(* Logix 5000 project; controller AMCI_3202_AOP_AOI_sample_RSLogix_V28 vendor 1 type 14 code 92 rev 28.11; software revision 28.00; part 3 of 3 *)
(* tags used below, declared in another part *)
   AMCI_3202_ch2_config_AOI : AMCI_3202_AOP_Configure;
   AMCI_3202_ch2_Home_CW_AOI : AMCI_3202_AOP_Home_CW;
   AMCI_3202_ch2_Manual_Move_CCW_AOI : AMCI_3202_AOP_Manual_Move_CCW;
   AMCI_3202_ch2_Manual_Move_CW_AOI : AMCI_3202_AOP_Manual_Move_CW;
   AMCI_3202_ch2_Preset_AOI : AMCI_3202_AOP_Preset;
   AMCI_3202_ch2_relative_move_AOI : AMCI_3202_AOP_Relative_Move;
   AMCI_3202_ch2_reset_errors_AOI : AMCI_3202_AOP_Reset_Errors;
   AMCI_3202_ch2_run_blend_AOI : AMCI_3202_AOP_Run_Blend;
   blend_message_3202_ch2 : MESSAGE;
   buffered_3202_data : DINT[16];
   comment : INT;
   run_3202_ch2 : INT;   // 1=Relative move 2=CW Manual Move 3=CCW Manual Move 4=Reset Errors 5=Home CW 6=Preset 7=Program Blend 8=Run Blend CW
(* MainProgram, continued *)

ROUTINE channel_2_3202   (* ladder *)
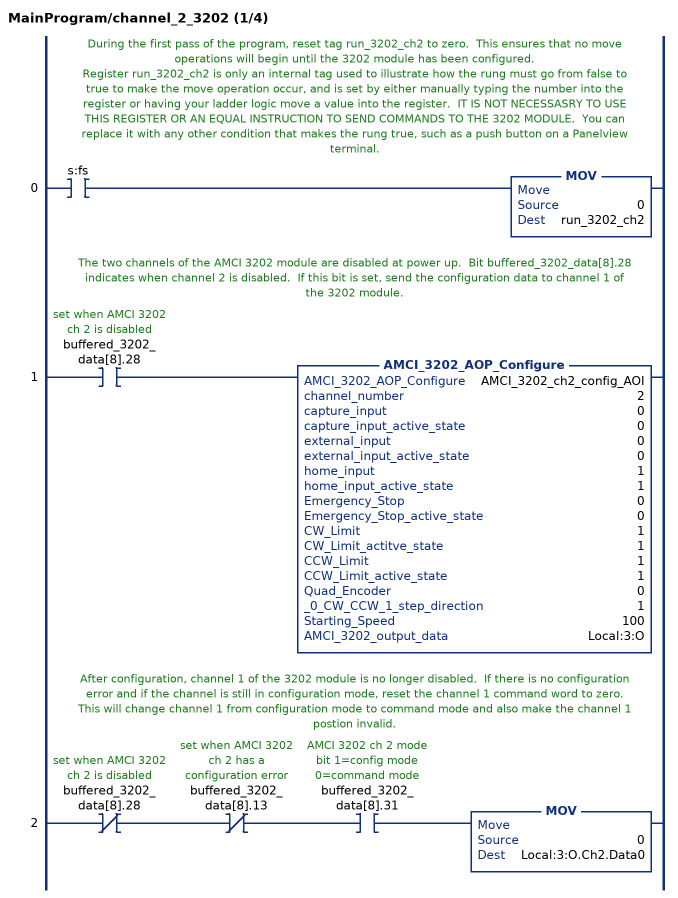
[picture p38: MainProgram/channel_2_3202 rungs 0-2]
   // During the first pass of the program, reset tag run_3202_ch2 to zero.  This ensures that no move operations will begin until the 3202 module has been configured.
   // Register run_3202_ch2 is only an internal tag used to illustrate how the rung must go from false to true to make the move operation occur, and is set by either manually typing the number into the register or having your ladder logic move a value into the register.  IT IS NOT NECESSASRY TO USE THIS REGISTER OR AN EQUAL INSTRUCTION TO SEND COMMANDS TO THE 3202 MODULE.  You can replace it with any other condition that makes the rung true, such as a push button on a Panelview terminal.
   0: XIC(s:fs)MOV(0,run_3202_ch2);
   // The two channels of the AMCI 3202 module are disabled at power up.  Bit buffered_3202_data[8].28 indicates when channel 2 is disabled.  If this bit is set, send the configuration data to channel 1 of the 3202 module.
   1: XIC(buffered_3202_data[8].28)AMCI_3202_AOP_Configure(AMCI_3202_ch2_config_AOI,2,0,0,0,0,1,1,0,0,1,1,1,1,0,1,100,Local:3:O);
   // After configuration, channel 1 of the 3202 module is no longer disabled.  If there is no configuration error and if the channel is still in configuration mode, reset the channel 1 command word to zero.  This will change channel 1 from configuration mode to command mode and also make the channel 1 postion invalid.
   2: XIO(buffered_3202_data[8].28)XIO(buffered_3202_data[8].13)XIC(buffered_3202_data[8].31)MOV(0,Local:3:O.Ch2.Data0);
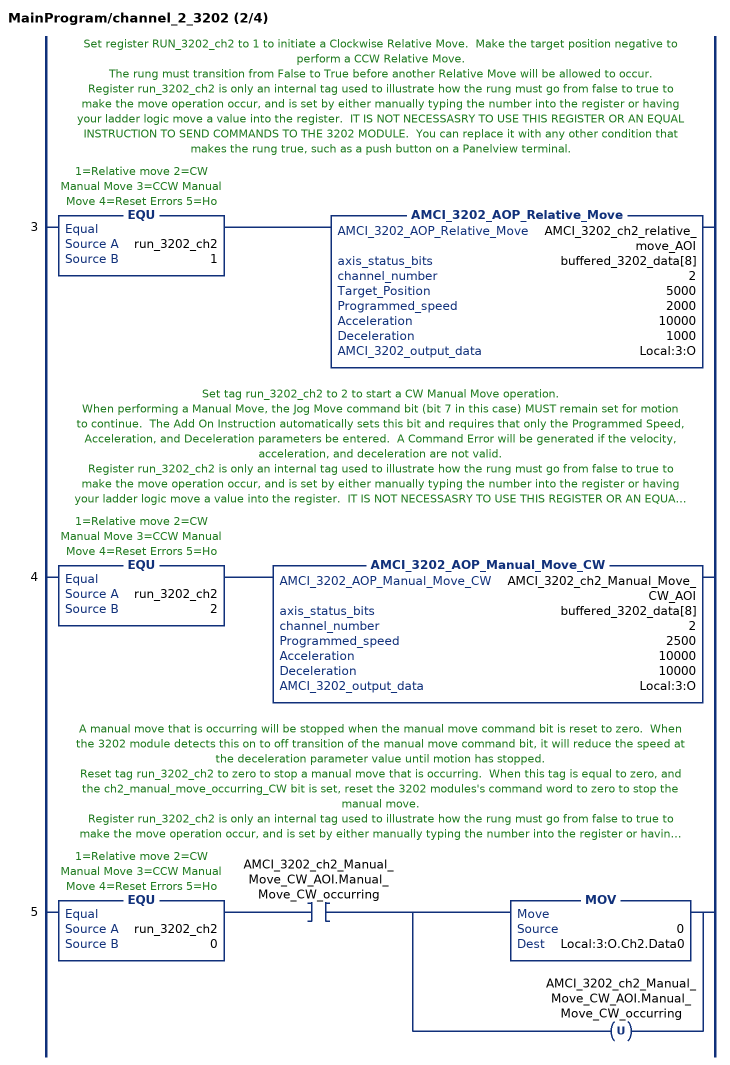
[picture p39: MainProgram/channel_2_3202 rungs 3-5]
   // Set register RUN_3202_ch2 to 1 to initiate a Clockwise Relative Move.  Make the target position negative to perform a CCW Relative Move.
   // The rung must transition from False to True before another Relative Move will be allowed to occur.
   // Register run_3202_ch2 is only an internal tag used to illustrate how the rung must go from false to true to make the move operation occur, and is set by either manually typing the number into the register or having your ladder logic move a value into the register.  IT IS NOT NECESSASRY TO USE THIS REGISTER OR AN EQUAL INSTRUCTION TO SEND COMMANDS TO THE 3202 MODULE.  You can replace it with any other condition that makes the rung true, such as a push button on a Panelview terminal.
   3: EQU(run_3202_ch2,1)AMCI_3202_AOP_Relative_Move(AMCI_3202_ch2_relative_move_AOI,buffered_3202_data[8],2,5000,2000,10000,1000,Local:3:O);
   // Set tag run_3202_ch2 to 2 to start a CW Manual Move operation.
   // When performing a Manual Move, the Jog Move command bit (bit 7 in this case) MUST remain set for motion to continue.  The Add On Instruction automatically sets this bit and requires that only the Programmed Speed, Acceleration, and Deceleration parameters be entered.  A Command Error will be generated if the velocity, acceleration, and deceleration are not valid.
   // Register run_3202_ch2 is only an internal tag used to illustrate how the rung must go from false to true to make the move operation occur, and is set by either manually typing the number into the register or having your ladder logic move a value into the register.  IT IS NOT NECESSASRY TO USE THIS REGISTER OR AN EQUAL INSTRUCTION TO SEND COMMANDS TO THE 3202 MODULE.  You can replace it with any other condition that makes the rung true, such as a push button on a Panelview terminal.
   4: EQU(run_3202_ch2,2)AMCI_3202_AOP_Manual_Move_CW(AMCI_3202_ch2_Manual_Move_CW_AOI,buffered_3202_data[8],2,2500,10000,10000,Local:3:O);
   // A manual move that is occurring will be stopped when the manual move command bit is reset to zero.  When the 3202 module detects this on to off transition of the manual move command bit, it will reduce the speed at the deceleration parameter value until motion has stopped.
   // Reset tag run_3202_ch2 to zero to stop a manual move that is occurring.  When this tag is equal to zero, and the ch2_manual_move_occurring_CW bit is set, reset the 3202 modules's command word to zero to stop the manual move.
   // Register run_3202_ch2 is only an internal tag used to illustrate how the rung must go from false to true to make the move operation occur, and is set by either manually typing the number into the register or having your ladder logic move a value into the register.  IT IS NOT NECESSASRY TO USE THIS REGISTER OR AN EQUAL INSTRUCTION TO SEND COMMANDS TO THE 3202 MODULE.  You can replace it with any other condition that makes the rung true, such as a push button on a Panelview terminal.
   5: EQU(run_3202_ch2,0)XIC(AMCI_3202_ch2_Manual_Move_CW_AOI.Manual_Move_CW_occurring)[MOV(0,Local:3:O.Ch2.Data0) ,OTU(AMCI_3202_ch2_Manual_Move_CW_AOI.Manual_Move_CW_occurring) ];
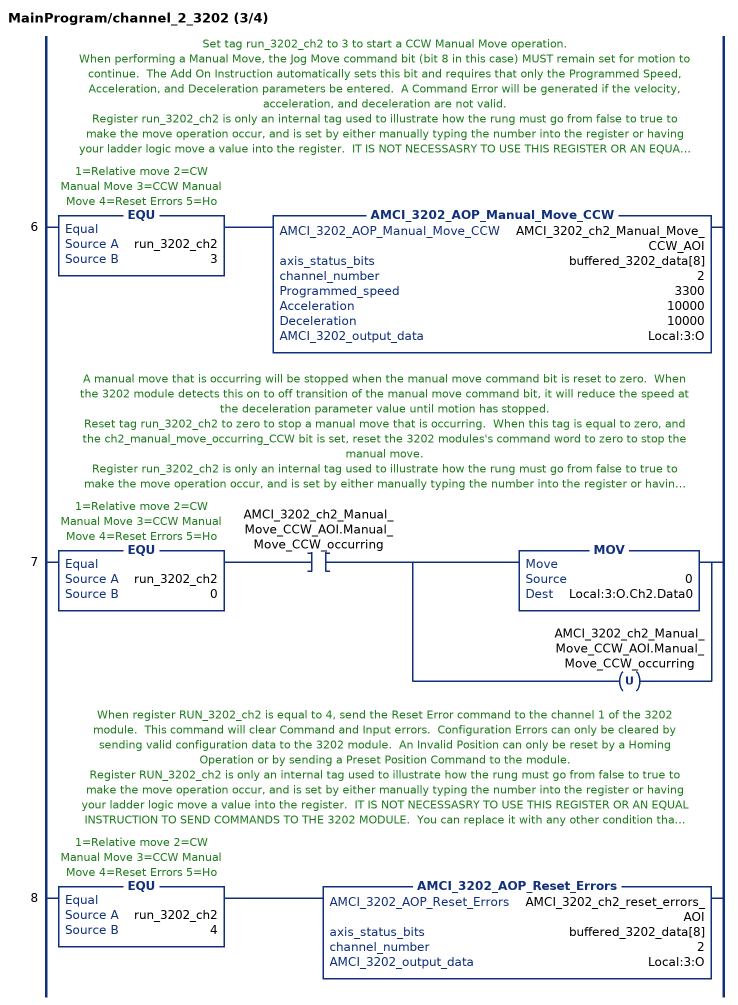
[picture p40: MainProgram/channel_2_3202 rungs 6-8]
   // Set tag run_3202_ch2 to 3 to start a CCW Manual Move operation.
   // When performing a Manual Move, the Jog Move command bit (bit 8 in this case) MUST remain set for motion to continue.  The Add On Instruction automatically sets this bit and requires that only the Programmed Speed, Acceleration, and Deceleration parameters be entered.  A Command Error will be generated if the velocity, acceleration, and deceleration are not valid.
   // Register run_3202_ch2 is only an internal tag used to illustrate how the rung must go from false to true to make the move operation occur, and is set by either manually typing the number into the register or having your ladder logic move a value into the register.  IT IS NOT NECESSASRY TO USE THIS REGISTER OR AN EQUAL INSTRUCTION TO SEND COMMANDS TO THE 3202 MODULE.  You can replace it with any other condition that makes the rung true, such as a push button on a Panelview terminal.
   6: EQU(run_3202_ch2,3)AMCI_3202_AOP_Manual_Move_CCW(AMCI_3202_ch2_Manual_Move_CCW_AOI,buffered_3202_data[8],2,3300,10000,10000,Local:3:O);
   // A manual move that is occurring will be stopped when the manual move command bit is reset to zero.  When the 3202 module detects this on to off transition of the manual move command bit, it will reduce the speed at the deceleration parameter value until motion has stopped.
   // Reset tag run_3202_ch2 to zero to stop a manual move that is occurring.  When this tag is equal to zero, and the ch2_manual_move_occurring_CCW bit is set, reset the 3202 modules's command word to zero to stop the manual move.
   // Register run_3202_ch2 is only an internal tag used to illustrate how the rung must go from false to true to make the move operation occur, and is set by either manually typing the number into the register or having your ladder logic move a value into the register.  IT IS NOT NECESSASRY TO USE THIS REGISTER OR AN EQUAL INSTRUCTION TO SEND COMMANDS TO THE 3202 MODULE.  You can replace it with any other condition that makes the rung true, such as a push button on a Panelview terminal.
   7: EQU(run_3202_ch2,0)XIC(AMCI_3202_ch2_Manual_Move_CCW_AOI.Manual_Move_CCW_occurring)[MOV(0,Local:3:O.Ch2.Data0) ,OTU(AMCI_3202_ch2_Manual_Move_CCW_AOI.Manual_Move_CCW_occurring) ];
   // When register RUN_3202_ch2 is equal to 4, send the Reset Error command to the channel 1 of the 3202 module.  This command will clear Command and Input errors.  Configuration Errors can only be cleared by sending valid configuration data to the 3202 module.  An Invalid Position can only be reset by a Homing Operation or by sending a Preset Position Command to the module.
   // Register RUN_3202_ch2 is only an internal tag used to illustrate how the rung must go from false to true to make the move operation occur, and is set by either manually typing the number into the register or having your ladder logic move a value into the register.  IT IS NOT NECESSASRY TO USE THIS REGISTER OR AN EQUAL INSTRUCTION TO SEND COMMANDS TO THE 3202 MODULE.  You can replace it with any other condition that makes the rung true, such as a push button on a Panelview terminal.
   8: EQU(run_3202_ch2,4)AMCI_3202_AOP_Reset_Errors(AMCI_3202_ch2_reset_errors_AOI,buffered_3202_data[8],2,Local:3:O);
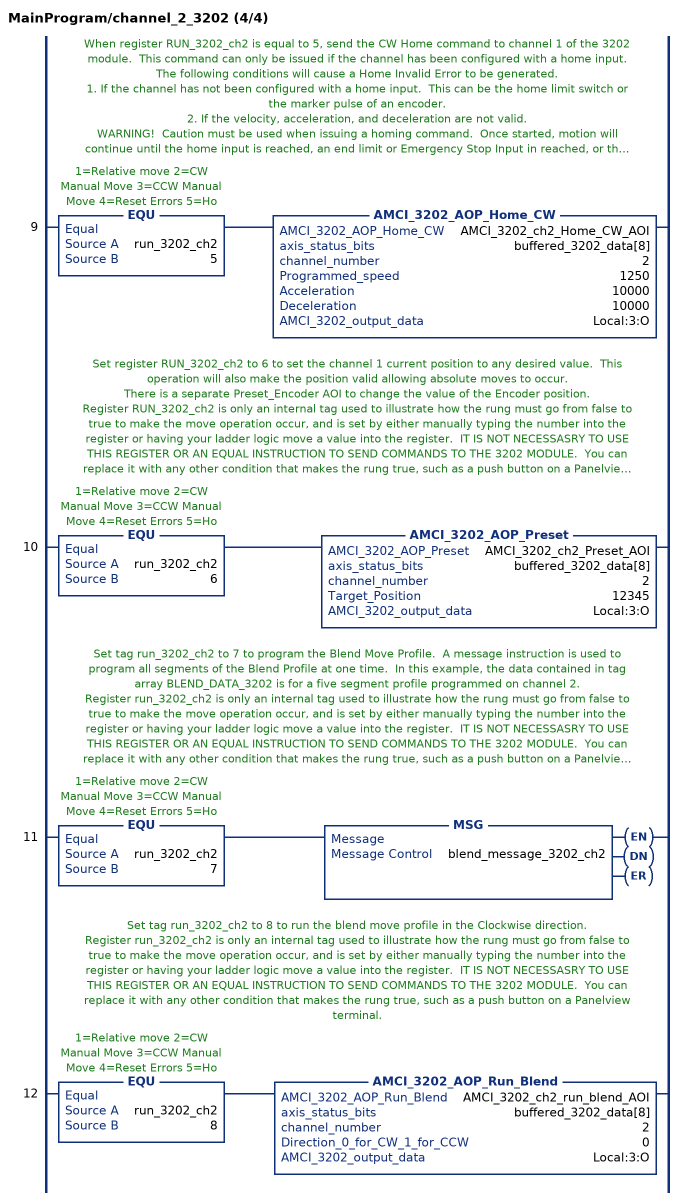
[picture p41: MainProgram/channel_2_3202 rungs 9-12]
   // When register RUN_3202_ch2 is equal to 5, send the CW Home command to channel 1 of the 3202 module.  This command can only be issued if the channel has been configured with a home input.  The following conditions will cause a Home Invalid Error to be generated.
   // 1. If the channel has not been configured with a home input.  This can be the home limit switch or the marker pulse of an encoder.
   // 2. If the velocity, acceleration, and deceleration are not valid.
   // WARNING!  Caution must be used when issuing a homing command.  Once started, motion will continue until the home input is reached, an end limit or Emergency Stop Input in reached, or the Immediate Stop Command is issued.  Resetting the command word to zero WILL NOT STOP a home operation.
   // Register RUN_3202_ch2 is only an internal tag used to illustrate how the rung must go from false to true to make the move operation occur, and is set by either manually typing the number into the register or having your ladder logic move a value into the register.  IT IS NOT NECESSASRY TO USE THIS REGISTER OR AN EQUAL INSTRUCTION TO SEND COMMANDS TO THE 3202 MODULE.  You can replace it with any other condition that makes the rung true, such as a push button on a Panelview terminal.
   9: EQU(run_3202_ch2,5)AMCI_3202_AOP_Home_CW(AMCI_3202_ch2_Home_CW_AOI,buffered_3202_data[8],2,1250,10000,10000,Local:3:O);
   // Set register RUN_3202_ch2 to 6 to set the channel 1 current position to any desired value.  This operation will also make the position valid allowing absolute moves to occur.
   // There is a separate Preset_Encoder AOI to change the value of the Encoder position.
   // Register RUN_3202_ch2 is only an internal tag used to illustrate how the rung must go from false to true to make the move operation occur, and is set by either manually typing the number into the register or having your ladder logic move a value into the register.  IT IS NOT NECESSASRY TO USE THIS REGISTER OR AN EQUAL INSTRUCTION TO SEND COMMANDS TO THE 3202 MODULE.  You can replace it with any other condition that makes the rung true, such as a push button on a Panelview terminal.
   10: EQU(run_3202_ch2,6)AMCI_3202_AOP_Preset(AMCI_3202_ch2_Preset_AOI,buffered_3202_data[8],2,12345,Local:3:O);
   // Set tag run_3202_ch2 to 7 to program the Blend Move Profile.  A message instruction is used to program all segments of the Blend Profile at one time.  In this example, the data contained in tag array BLEND_DATA_3202 is for a five segment profile programmed on channel 2.
   // Register run_3202_ch2 is only an internal tag used to illustrate how the rung must go from false to true to make the move operation occur, and is set by either manually typing the number into the register or having your ladder logic move a value into the register.  IT IS NOT NECESSASRY TO USE THIS REGISTER OR AN EQUAL INSTRUCTION TO SEND COMMANDS TO THE 3202 MODULE.  You can replace it with any other condition that makes the rung true, such as a push button on a Panelview terminal.
   11: EQU(run_3202_ch2,7)MSG(blend_message_3202_ch2);
   // Set tag run_3202_ch2 to 8 to run the blend move profile in the Clockwise direction.
   // Register run_3202_ch2 is only an internal tag used to illustrate how the rung must go from false to true to make the move operation occur, and is set by either manually typing the number into the register or having your ladder logic move a value into the register.  IT IS NOT NECESSASRY TO USE THIS REGISTER OR AN EQUAL INSTRUCTION TO SEND COMMANDS TO THE 3202 MODULE.  You can replace it with any other condition that makes the rung true, such as a push button on a Panelview terminal.
   12: EQU(run_3202_ch2,8)AMCI_3202_AOP_Run_Blend(AMCI_3202_ch2_run_blend_AOI,buffered_3202_data[8],2,0,Local:3:O);
END_ROUTINE

ROUTINE MainRoutine   (* ladder *)
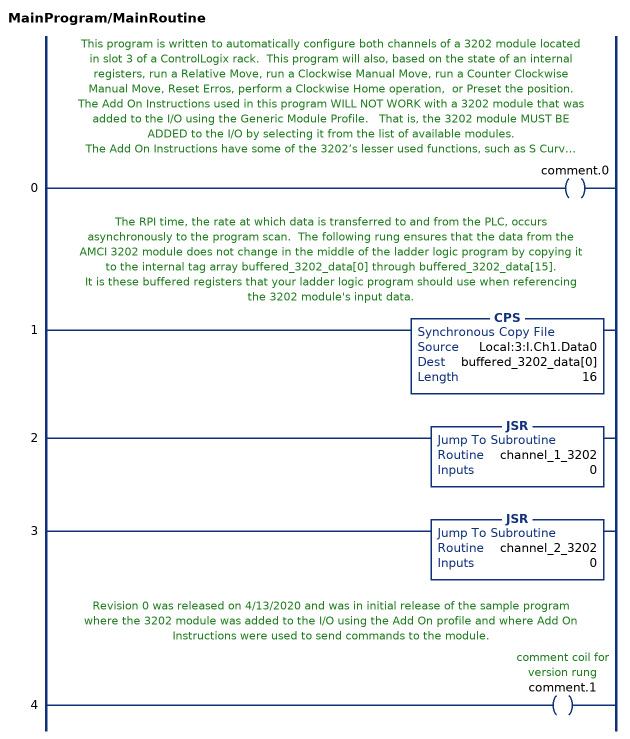
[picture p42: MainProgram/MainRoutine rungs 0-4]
   // This program is written to automatically configure both channels of a 3202 module located in slot 3 of a ControlLogix rack.  This program will also, based on the state of an internal registers, run a Relative Move, run a Clockwise Manual Move, run a Counter Clockwise Manual Move, Reset Erros, perform a Clockwise Home operation,  or Preset the position.
   // The Add On Instructions used in this program WILL NOT WORK with a 3202 module that was added to the I/O using the Generic Module Profile.   That is, the 3202 module MUST BE ADDED to the I/O by selecting it from the list of available modules.
   // The Add On Instructions have some of the 3202’s lesser used functions, such as S Curve Acceleration, hidden.  The Add On Instructions are not locked or protected and, if desired, these functions can be enabled and made visible.
   // This program also contains logic to program and perform blend moves.  This logic is optional and if not needed, can be deleted or ignored.
   // Registers RUN_3202_channel_1 and RUN_3202_channel_2  are only internal tags used to illustrate how the rung must go from false to true to make the move operation occur, and is set by either manually typing the number into the register or having your ladder logic move a value into the register.  IT IS NOT NECESSASRY TO USE these REGISTER OR AN EQUAL INSTRUCTION TO SEND COMMANDS TO THE 3202 MODULE.  You can replace it with any other condition that makes the rung true, such as a push button on a Panelview terminal.
   0: OTE(comment.0);
   // The RPI time, the rate at which data is transferred to and from the PLC, occurs asynchronously to the program scan.  The following rung ensures that the data from the AMCI 3202 module does not change in the middle of the ladder logic program by copying it to the internal tag array buffered_3202_data[0] through buffered_3202_data[15].
   // It is these buffered registers that your ladder logic program should use when referencing the 3202 module's input data.
   1: CPS(Local:3:I.Ch1.Data0,buffered_3202_data[0],16);
   2: JSR(channel_1_3202,0);
   3: JSR(channel_2_3202,0);
   // Revision 0 was released on 4/13/2020 and was in initial release of the sample program where the 3202 module was added to the I/O using the Add On profile and where Add On Instructions were used to send commands to the module.
   4: OTE(comment.1);
END_ROUTINE
END_PROGRAM
